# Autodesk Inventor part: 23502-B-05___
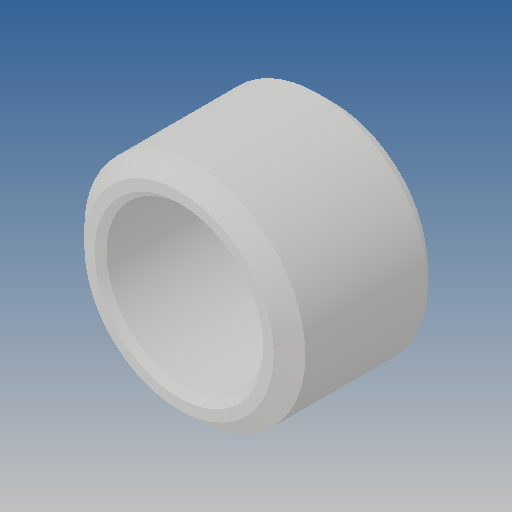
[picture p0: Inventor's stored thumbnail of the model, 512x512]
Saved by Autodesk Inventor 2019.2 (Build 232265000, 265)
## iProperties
Created: 2010-06
Part Number: 23502-B-05___
Material: Ogólny
Document SubType Name: Modeling
Designer: CADENGINEERING4
Density: 1 g/cm^3
Appearance: Domyślna
Author: CADENGINEERING4
Revision Number: ANY
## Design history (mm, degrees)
feature "NONE"
node "Bryła1"
